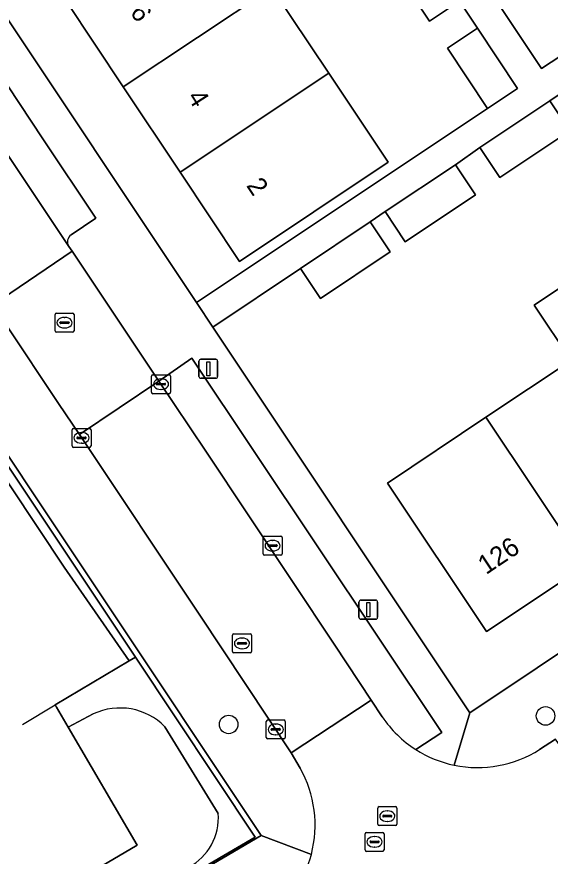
# Model space of a CAD drawing. Extents: x 158352 to 159489, y 383828 to 384603.
# Drawn here: x 158728.21 to 158756.34, y 384163.88 to 384208.09 of the extents above; entities that cross this region are included whole.
import ezdxf

# ---------------------------------------------------------------- set-up
doc = ezdxf.new("R2010")
doc.units = 0
for name, color, linetype in [('IMGEO_Boom', 7, 'Continuous'), ('IMGEO_Erf', 7, 'Continuous'), ('IMGEO_Groenvoorziening', 7, 'Continuous'), ('IMGEO_Hek', 7, 'Continuous'), ('IMGEO_Kolk', 7, 'Continuous'), ('IMGEO_Lichtmast', 7, 'Continuous'), ('IMGEO_Pand', 7, 'Continuous'), ('IMGEO_Pand_nummerreeks', 7, 'Continuous'), ('IMGEO_Parkeervlak_open', 7, 'Continuous'), ('IMGEO_Rijbaan_lokaal_open', 7, 'Continuous'), ('IMGEO_Rioolput', 7, 'Continuous'), ('IMGEO_Voetpad_open', 7, 'Continuous')]:
    doc.layers.add(name, color=color, linetype=linetype)

msp = doc.modelspace()

# ---------------------------------------------------------------- linework, layer by layer
at = {"layer": 'IMGEO_Boom'}
for centre in [(158756.089, 384171.265), (158739.383, 384170.816)]:
    msp.add_circle(centre, 0.489, dxfattribs=at)
at = {"layer": 'IMGEO_Erf'}
for points in [[(158661.89, 384306.702), (158737.694, 384193.032), (158753.032, 384203.26), (158750.922, 384206.438), (158752.505, 384207.489), (158751.552, 384208.904), (158749.972, 384207.85), (158747.497, 384211.561)], [(158766.842, 384208.399), (158763.158, 384205.927), (158762.099, 384207.505), (158761.301, 384206.989), (158762.358, 384205.41), (158758.66, 384202.935), (158757.603, 384204.514), (158756.312, 384203.657), (158757.363, 384202.077), (158753.675, 384199.623), (158752.622, 384201.206), (158751.342, 384200.289), (158752.394, 384198.707), (158748.69, 384196.244), (158747.638, 384197.826), (158746.844, 384197.289), (158747.9, 384195.71), (158744.228, 384193.253), (158743.172, 384194.832), (158738.549, 384191.749), (158752.1, 384171.43), (158802.113, 384204.829), (158788.594, 384225.155)], [(158732.078, 384163.004), (158734.56, 384164.453), (158730.926, 384170.674), (158730.313, 384171.723), (158730.24, 384171.849), (158734.136, 384174.169), (158730.72, 384179.098), (158723.614, 384189.764), (158724.023, 384190.002), (158700.665, 384224.966)], [(158741.664, 384209.617), (158744.664, 384205.122), (158747.791, 384200.432), (158739.959, 384195.193), (158736.823, 384199.899), (158733.825, 384204.395), (158730.828, 384208.891)]]:
    msp.add_lwpolyline(points, dxfattribs=at)
msp.add_lwpolyline([(158762.429, 384193.318), (158767.425, 384196.648), (158771.909, 384199.638), (158776.904, 384202.967), (158781.884, 384206.291), (158786.38, 384209.294), (158792.699, 384213.514), (158795.295, 384209.606), (158794.187, 384208.841), (158796.785, 384204.942), (158791.593, 384201.478), (158787.135, 384198.42), (158782.117, 384195.154), (158777.123, 384191.822), (158772.673, 384188.781), (158767.646, 384185.498), (158762.68, 384182.121), (158758.17, 384179.174), (158752.974, 384175.706), (158747.751, 384183.533), (158752.949, 384186.999), (158757.435, 384189.983), (158755.483, 384192.906), (158760.477, 384196.241)], close=True, dxfattribs=at)
at = {"layer": 'IMGEO_Groenvoorziening'}
for points in [[(158734.468, 384174.367), (158740.785, 384164.877), (158709.334, 384146.504), (158709.408, 384146.369), (158741.091, 384164.958), (158724.283, 384190.153), (158724.023, 384190.002)], [(158724.023, 384190.002), (158723.614, 384189.764), (158730.72, 384179.098), (158734.136, 384174.169), (158734.468, 384174.367)]]:
    msp.add_lwpolyline(points, close=True, dxfattribs=at)
for points in [[(158737.445, 384190.113), (158735.708, 384188.905), (158738.187, 384185.214), (158744.988, 384174.983), (158746.896, 384172.098), (158747.48, 384171.214)], [(158749.247, 384169.495), (158750.617, 384170.393), (158737.445, 384190.113)], [(158740.785, 384164.877), (158734.468, 384174.367), (158734.136, 384174.169), (158730.24, 384171.849), (158730.313, 384171.723), (158730.926, 384170.674), (158732.248, 384171.369)], [(158732.248, 384171.369), (158730.926, 384170.674)], [(158730.926, 384170.674), (158734.56, 384164.453), (158732.078, 384163.004)], [(158736.023, 384170.696), (158738.832, 384166.131)], [(158738.832, 384166.131), (158736.023, 384170.696)], [(158737.281, 384163.293), (158733.448, 384161.127), (158731.081, 384159.768), (158721.07, 384154.017), (158720.134, 384154.397), (158718.086, 384153.373), (158717.208, 384152.173), (158716.184, 384151.5), (158715.101, 384151.178), (158714.37, 384151.178), (158710.698, 384149.022), (158711.217, 384148.102), (158709.118, 384146.897), (158709.334, 384146.504), (158740.785, 384164.877)]]:
    msp.add_lwpolyline(points, dxfattribs=at)
for centre, radius, start, end in [((158733.658, 384168.357), 3.326, 44.6918, 115.0914), ((158733.658, 384168.357), 3.326, 44.6918, 115.0914), ((158752.54, 384174.647), 6.115, 214.1597, 237.418), ((158735.866, 384165.909), 2.974, 298.4051, 4.2806), ((158735.866, 384165.909), 2.974, 298.4051, 4.2806)]:
    msp.add_arc(centre, radius, start, end, dxfattribs=at)
at = {"layer": 'IMGEO_Hek'}
for points in [[(158734.468, 384174.367), (158724.023, 384190.002)], [(158730.24, 384171.849), (158734.136, 384174.169), (158734.468, 384174.367)], [(158740.785, 384164.877), (158734.468, 384174.367)], [(158728.508, 384170.817), (158730.24, 384171.849)], [(158709.334, 384146.504), (158740.785, 384164.877)]]:
    msp.add_lwpolyline(points, dxfattribs=at)
at = {"layer": 'IMGEO_Kolk'}
for p, q in [((158735.318, 384188.312), (158735.318, 384189.164)), ((158735.393, 384189.238), (158736.245, 384189.238)), ((158735.806, 384189.018), (158735.831, 384189.018)), ((158736.319, 384189.164), (158736.319, 384188.312)), ((158735.577, 384188.732), (158735.577, 384188.744)), ((158736.015, 384188.695), (158735.617, 384188.695)), ((158735.62, 384188.781), (158736.018, 384188.781)), ((158735.829, 384188.458), (158735.804, 384188.458)), ((158736.061, 384188.744), (158736.061, 384188.732)), ((158736.245, 384188.238), (158735.393, 384188.238)), ((158731.127, 384185.484), (158731.127, 384186.336)), ((158731.202, 384186.41), (158732.054, 384186.41)), ((158732.128, 384186.336), (158732.128, 384185.484)), ((158731.386, 384185.904), (158731.386, 384185.916)), ((158731.824, 384185.867), (158731.426, 384185.867)), ((158731.429, 384185.953), (158731.827, 384185.953)), ((158731.615, 384186.19), (158731.64, 384186.19)), ((158731.87, 384185.916), (158731.87, 384185.904)), ((158732.054, 384185.41), (158731.202, 384185.41)), ((158731.638, 384185.63), (158731.613, 384185.63)), ((158741.2, 384179.806), (158741.2, 384180.658)), ((158741.275, 384180.732), (158742.127, 384180.732)), ((158741.688, 384180.512), (158741.713, 384180.512)), ((158742.201, 384180.658), (158742.201, 384179.806)), ((158741.459, 384180.226), (158741.459, 384180.238)), ((158741.897, 384180.189), (158741.499, 384180.189)), ((158741.502, 384180.275), (158741.9, 384180.275)), ((158741.943, 384180.238), (158741.943, 384180.226)), ((158742.127, 384179.732), (158741.275, 384179.732)), ((158741.711, 384179.952), (158741.686, 384179.952)), ((158741.365, 384170.127), (158741.365, 384170.979)), ((158741.44, 384171.053), (158742.292, 384171.053)), ((158741.853, 384170.833), (158741.878, 384170.833)), ((158742.366, 384170.979), (158742.366, 384170.127)), ((158741.624, 384170.547), (158741.624, 384170.559)), ((158742.062, 384170.51), (158741.664, 384170.51)), ((158741.667, 384170.596), (158742.065, 384170.596)), ((158742.108, 384170.559), (158742.108, 384170.547)), ((158742.292, 384170.053), (158741.44, 384170.053)), ((158741.876, 384170.273), (158741.851, 384170.273))]:
    msp.add_line(p, q, dxfattribs=at)
for points in [[(158735.318, 384188.312), (158735.318, 384189.164)], [(158735.393, 384189.238), (158736.245, 384189.238)], [(158736.319, 384189.164), (158736.319, 384188.312)], [(158736.245, 384188.238), (158735.393, 384188.238)], [(158731.127, 384185.484), (158731.127, 384186.336)], [(158731.202, 384186.41), (158732.054, 384186.41)], [(158732.128, 384186.336), (158732.128, 384185.484)], [(158732.054, 384185.41), (158731.202, 384185.41)], [(158741.2, 384179.806), (158741.2, 384180.658)], [(158741.275, 384180.732), (158742.127, 384180.732)], [(158742.201, 384180.658), (158742.201, 384179.806)], [(158742.127, 384179.732), (158741.275, 384179.732)], [(158741.365, 384170.127), (158741.365, 384170.979)], [(158741.44, 384171.053), (158742.292, 384171.053)], [(158742.366, 384170.979), (158742.366, 384170.127)], [(158742.292, 384170.053), (158741.44, 384170.053)]]:
    msp.add_lwpolyline(points, dxfattribs=at)
for centre, radius, start, end in [((158735.395, 384189.162), 0.0765, 91.552, 178.448), ((158735.395, 384189.162), 0.0765, 91.552, 178.448), ((158736.243, 384189.162), 0.0765, 1.552, 88.448), ((158736.243, 384189.162), 0.0765, 1.552, 88.448), ((158735.617, 384188.741), 0.0403, 85.8775, 175.7526), ((158735.614, 384188.731), 0.0366, 178.938, 274.7102), ((158736.018, 384188.738), 0.043, 264.8664, 352.4533), ((158736.022, 384188.743), 0.0386, 1.7309, 96.639), ((158735.395, 384188.314), 0.0765, 181.552, 268.448), ((158735.395, 384188.314), 0.0765, 181.552, 268.448), ((158736.243, 384188.314), 0.0765, 271.552, 358.448), ((158736.243, 384188.314), 0.0765, 271.552, 358.448), ((158731.204, 384186.334), 0.0765, 91.552, 178.448), ((158731.204, 384186.334), 0.0765, 91.552, 178.448), ((158732.052, 384186.334), 0.0765, 1.552, 88.448), ((158732.052, 384186.334), 0.0765, 1.552, 88.448), ((158731.426, 384185.913), 0.0403, 85.8775, 175.7526), ((158731.423, 384185.903), 0.0366, 178.938, 274.7102), ((158731.827, 384185.91), 0.043, 264.8664, 352.4533), ((158731.831, 384185.915), 0.0386, 1.7309, 96.639), ((158731.204, 384185.486), 0.0765, 181.552, 268.448), ((158731.204, 384185.486), 0.0765, 181.552, 268.448), ((158732.052, 384185.486), 0.0765, 271.552, 358.448), ((158732.052, 384185.486), 0.0765, 271.552, 358.448), ((158741.277, 384180.656), 0.0765, 91.552, 178.448), ((158741.277, 384180.656), 0.0765, 91.552, 178.448), ((158742.125, 384180.656), 0.0765, 1.552, 88.448), ((158742.125, 384180.656), 0.0765, 1.552, 88.448), ((158741.499, 384180.235), 0.0403, 85.8775, 175.7526), ((158741.496, 384180.225), 0.0366, 178.938, 274.7102), ((158741.9, 384180.232), 0.043, 264.8664, 352.4533), ((158741.904, 384180.237), 0.0386, 1.7309, 96.639), ((158741.277, 384179.808), 0.0765, 181.552, 268.448), ((158741.277, 384179.808), 0.0765, 181.552, 268.448), ((158742.125, 384179.808), 0.0765, 271.552, 358.448), ((158742.125, 384179.808), 0.0765, 271.552, 358.448), ((158741.442, 384170.977), 0.0765, 91.552, 178.448), ((158741.442, 384170.977), 0.0765, 91.552, 178.448), ((158742.29, 384170.977), 0.0765, 1.552, 88.448), ((158742.29, 384170.977), 0.0765, 1.552, 88.448), ((158741.664, 384170.556), 0.0403, 85.8775, 175.7526), ((158741.661, 384170.546), 0.0366, 178.938, 274.7102), ((158742.065, 384170.553), 0.043, 264.8664, 352.4533), ((158742.069, 384170.558), 0.0386, 1.7309, 96.639), ((158741.442, 384170.129), 0.0765, 181.552, 268.448), ((158741.442, 384170.129), 0.0765, 181.552, 268.448), ((158742.29, 384170.129), 0.0765, 271.552, 358.448), ((158742.29, 384170.129), 0.0765, 271.552, 358.448)]:
    msp.add_arc(centre, radius, start, end, dxfattribs=at)
for centre, major_axis, ratio, start_param, end_param in [((158735.805, 384188.738), (-0.387, 0.002), 0.722429, 4.712389, 7.853982), ((158735.83, 384188.738), (-0.39, 0.002), 0.717154, 1.570796, 4.712389), ((158731.614, 384185.91), (-0.387, 0.002), 0.722429, 4.712389, 7.853982), ((158731.639, 384185.91), (-0.39, 0.002), 0.717154, 1.570796, 4.712389), ((158741.687, 384180.232), (-0.387, 0.002), 0.722429, 4.712389, 7.853982), ((158741.712, 384180.232), (-0.39, 0.002), 0.717154, 1.570796, 4.712389), ((158741.852, 384170.553), (-0.387, 0.002), 0.722429, 4.712389, 7.853982), ((158741.877, 384170.553), (-0.39, 0.002), 0.717154, 1.570796, 4.712389)]:
    msp.add_ellipse(centre, major_axis=major_axis, ratio=ratio, start_param=start_param, end_param=end_param, dxfattribs=at)
at = {"layer": 'IMGEO_Lichtmast'}
for p, q in [((158737.813, 384189.147), (158737.813, 384189.947)), ((158737.813, 384189.947), (158737.813, 384189.147)), ((158737.913, 384190.047), (158738.703, 384190.047)), ((158738.703, 384190.047), (158737.913, 384190.047)), ((158738.803, 384189.947), (158738.803, 384189.147)), ((158738.803, 384189.147), (158738.803, 384189.947)), ((158738.703, 384189.047), (158737.913, 384189.047)), ((158737.913, 384189.047), (158738.703, 384189.047)), ((158746.248, 384176.461), (158746.248, 384177.261)), ((158746.248, 384177.261), (158746.248, 384176.461)), ((158746.348, 384177.361), (158747.138, 384177.361)), ((158747.138, 384177.361), (158746.348, 384177.361)), ((158747.238, 384177.261), (158747.238, 384176.461)), ((158747.238, 384176.461), (158747.238, 384177.261)), ((158747.138, 384176.361), (158746.348, 384176.361)), ((158746.348, 384176.361), (158747.138, 384176.361))]:
    msp.add_line(p, q, dxfattribs=at)
for points in [[(158738.233, 384189.922), (158738.383, 384189.922), (158738.383, 384189.172), (158738.233, 384189.172), (158738.233, 384189.922)], [(158746.668, 384177.236), (158746.818, 384177.236), (158746.818, 384176.486), (158746.668, 384176.486), (158746.668, 384177.236)]]:
    msp.add_lwpolyline(points, dxfattribs=at)
for centre, start, end in [((158737.913, 384189.947), 90, 180), ((158737.913, 384189.947), 90, 180), ((158738.703, 384189.947), 0, 90), ((158738.703, 384189.947), 360, 90), ((158737.913, 384189.147), 180, 270), ((158737.913, 384189.147), 180, 270), ((158738.703, 384189.147), 270, 0), ((158738.703, 384189.147), 270, 0), ((158746.348, 384177.261), 90, 180), ((158746.348, 384177.261), 90, 180), ((158747.138, 384177.261), 0, 90), ((158747.138, 384177.261), 360, 90), ((158746.348, 384176.461), 180, 270), ((158746.348, 384176.461), 180, 270), ((158747.138, 384176.461), 270, 0), ((158747.138, 384176.461), 270, 0)]:
    msp.add_arc(centre, 0.1, start, end, dxfattribs=at)
at = {"layer": 'IMGEO_Pand'}
for points in [[(158741.664, 384209.617), (158741.545, 384209.795), (158743.534, 384211.122), (158740.737, 384215.314), (158738.748, 384213.988), (158738.665, 384214.113), (158730.828, 384208.891), (158733.825, 384204.395)], [(158749.972, 384207.85), (158751.552, 384208.904), (158749.077, 384212.615), (158747.497, 384211.561)], [(158733.825, 384204.395), (158736.823, 384199.899), (158744.664, 384205.122), (158741.664, 384209.617)], [(158753.032, 384203.26), (158754.615, 384204.311), (158752.505, 384207.489), (158750.922, 384206.438)], [(158744.664, 384205.122), (158736.823, 384199.899), (158739.959, 384195.193), (158747.791, 384200.432)], [(158753.675, 384199.623), (158757.363, 384202.077), (158756.312, 384203.657), (158752.622, 384201.206)], [(158748.69, 384196.244), (158752.394, 384198.707), (158751.342, 384200.289), (158747.638, 384197.826)], [(158744.228, 384193.253), (158747.9, 384195.71), (158746.844, 384197.289), (158743.172, 384194.832)], [(158762.429, 384193.318), (158760.477, 384196.241), (158755.483, 384192.906), (158757.435, 384189.983), (158762.68, 384182.121), (158767.646, 384185.498)], [(158762.68, 384182.121), (158757.435, 384189.983), (158752.949, 384186.999), (158758.17, 384179.174)], [(158752.949, 384186.999), (158747.751, 384183.533), (158752.974, 384175.706), (158758.17, 384179.174)]]:
    msp.add_lwpolyline(points, close=True, dxfattribs=at)
at = {"layer": 'IMGEO_Parkeervlak_open'}
for points in [[(158731.078, 384196.607), (158732.384, 384197.474), (158729.586, 384201.665), (158723.424, 384210.977), (158701.545, 384243.711)], [(158699.65, 384242.943), (158727.586, 384201.054), (158730.963, 384195.982)], [(158745.185, 384229.466), (158741.472, 384226.964), (158755.874, 384205.363), (158760.063, 384208.099), (158745.402, 384230.033)]]:
    msp.add_lwpolyline(points, dxfattribs=at)
msp.add_arc((158731.352, 384196.233), 0.463, 126.2731, 212.8753, dxfattribs=at)
at = {"layer": 'IMGEO_Rijbaan_lokaal_open'}
for points in [[(158699.65, 384242.943), (158697.726, 384245.831), (158693.511, 384243.056), (158726.672, 384193.344), (158726.698, 384193.304), (158726.954, 384192.921), (158731.127, 384195.741), (158730.963, 384195.982), (158727.586, 384201.054)], [(158731.127, 384195.741), (158726.954, 384192.921), (158727.659, 384191.863), (158730.422, 384187.719), (158731.514, 384186.085), (158735.708, 384188.905)], [(158738.187, 384185.214), (158735.708, 384188.905), (158731.514, 384186.085), (158737.872, 384176.577), (158742.673, 384169.326), (158746.896, 384172.098), (158744.988, 384174.983)]]:
    msp.add_lwpolyline(points, close=True, dxfattribs=at)
for points in [[(158747.48, 384171.214), (158746.896, 384172.098), (158742.673, 384169.326), (158743.162, 384168.514)], [(158753.215, 384162.703), (158754.1, 384161.357), (158756.455, 384162.969), (158759.872, 384165.217), (158759.023, 384166.554), (158757.561, 384168.674), (158756.613, 384170.048), (158755.775, 384169.498)]]:
    msp.add_lwpolyline(points, dxfattribs=at)
for centre, radius, start, end in [((158752.54, 384174.647), 6.115, 214.1597, 237.418), ((158752.514, 384174.628), 6.085, 237.5202, 258.2851), ((158752.508, 384174.62), 6.075, 258.3337, 302.5361), ((158737.767, 384165.514), 6.173, 345.5251, 29.0756), ((158737.7, 384165.596), 6.258, 301.9381, 344.9514)]:
    msp.add_arc(centre, radius, start, end, dxfattribs=at)
at = {"layer": 'IMGEO_Rioolput'}
for p, q in [((158730.308, 384192.477), (158731.16, 384192.477)), ((158730.233, 384191.551), (158730.233, 384192.403)), ((158730.492, 384191.971), (158730.492, 384191.983)), ((158730.535, 384192.02), (158730.933, 384192.02)), ((158730.721, 384192.257), (158730.746, 384192.257)), ((158730.976, 384191.983), (158730.976, 384191.971)), ((158731.234, 384192.403), (158731.234, 384191.551)), ((158730.93, 384191.934), (158730.532, 384191.934)), ((158730.744, 384191.697), (158730.719, 384191.697)), ((158731.16, 384191.477), (158730.308, 384191.477)), ((158739.585, 384174.659), (158739.585, 384175.511)), ((158739.66, 384175.585), (158740.512, 384175.585)), ((158740.073, 384175.365), (158740.098, 384175.365)), ((158740.586, 384175.511), (158740.586, 384174.659)), ((158739.844, 384175.079), (158739.844, 384175.091)), ((158740.282, 384175.042), (158739.884, 384175.042)), ((158739.887, 384175.128), (158740.285, 384175.128)), ((158740.096, 384174.805), (158740.071, 384174.805)), ((158740.328, 384175.091), (158740.328, 384175.079)), ((158740.512, 384174.585), (158739.66, 384174.585)), ((158747.246, 384165.56), (158747.246, 384166.412)), ((158747.321, 384166.486), (158748.173, 384166.486)), ((158748.247, 384166.412), (158748.247, 384165.56)), ((158747.505, 384165.98), (158747.505, 384165.992)), ((158747.943, 384165.943), (158747.545, 384165.943)), ((158747.548, 384166.029), (158747.946, 384166.029)), ((158747.734, 384166.266), (158747.759, 384166.266)), ((158747.989, 384165.992), (158747.989, 384165.98)), ((158748.173, 384165.486), (158747.321, 384165.486)), ((158747.757, 384165.706), (158747.732, 384165.706)), ((158746.576, 384164.206), (158746.576, 384165.058)), ((158746.651, 384165.132), (158747.503, 384165.132)), ((158747.577, 384165.058), (158747.577, 384164.206)), ((158746.835, 384164.626), (158746.835, 384164.638)), ((158747.273, 384164.589), (158746.875, 384164.589)), ((158746.878, 384164.675), (158747.276, 384164.675)), ((158747.064, 384164.912), (158747.089, 384164.912)), ((158747.319, 384164.638), (158747.319, 384164.626)), ((158747.503, 384164.132), (158746.651, 384164.132)), ((158747.087, 384164.352), (158747.062, 384164.352))]:
    msp.add_line(p, q, dxfattribs=at)
for points in [[(158730.308, 384192.477), (158731.16, 384192.477)], [(158730.233, 384191.551), (158730.233, 384192.403)], [(158731.234, 384192.403), (158731.234, 384191.551)], [(158731.16, 384191.477), (158730.308, 384191.477)], [(158739.585, 384174.659), (158739.585, 384175.511)], [(158739.66, 384175.585), (158740.512, 384175.585)], [(158740.586, 384175.511), (158740.586, 384174.659)], [(158740.512, 384174.585), (158739.66, 384174.585)], [(158747.246, 384165.56), (158747.246, 384166.412)], [(158747.321, 384166.486), (158748.173, 384166.486)], [(158748.247, 384166.412), (158748.247, 384165.56)], [(158748.173, 384165.486), (158747.321, 384165.486)], [(158746.576, 384164.206), (158746.576, 384165.058)], [(158746.651, 384165.132), (158747.503, 384165.132)], [(158747.577, 384165.058), (158747.577, 384164.206)], [(158747.503, 384164.132), (158746.651, 384164.132)]]:
    msp.add_lwpolyline(points, dxfattribs=at)
for centre, radius, start, end in [((158730.31, 384192.401), 0.0765, 91.552, 178.448), ((158730.31, 384192.401), 0.0765, 91.552, 178.448), ((158731.158, 384192.401), 0.0765, 1.552, 88.448), ((158731.158, 384192.401), 0.0765, 1.552, 88.448), ((158730.532, 384191.98), 0.0403, 85.8775, 175.7526), ((158730.937, 384191.982), 0.0386, 1.7309, 96.639), ((158730.31, 384191.553), 0.0765, 181.552, 268.448), ((158730.31, 384191.553), 0.0765, 181.552, 268.448), ((158730.529, 384191.97), 0.0366, 178.938, 274.7102), ((158730.933, 384191.977), 0.043, 264.8664, 352.4533), ((158731.158, 384191.553), 0.0765, 271.552, 358.448), ((158731.158, 384191.553), 0.0765, 271.552, 358.448), ((158739.662, 384175.509), 0.0765, 91.552, 178.448), ((158739.662, 384175.509), 0.0765, 91.552, 178.448), ((158740.51, 384175.509), 0.0765, 1.552, 88.448), ((158740.51, 384175.509), 0.0765, 1.552, 88.448), ((158739.884, 384175.088), 0.0403, 85.8775, 175.7526), ((158739.881, 384175.078), 0.0366, 178.938, 274.7102), ((158740.285, 384175.085), 0.043, 264.8664, 352.4533), ((158740.289, 384175.09), 0.0386, 1.7309, 96.639), ((158739.662, 384174.661), 0.0765, 181.552, 268.448), ((158739.662, 384174.661), 0.0765, 181.552, 268.448), ((158740.51, 384174.661), 0.0765, 271.552, 358.448), ((158740.51, 384174.661), 0.0765, 271.552, 358.448), ((158747.323, 384166.41), 0.0765, 91.552, 178.448), ((158747.323, 384166.41), 0.0765, 91.552, 178.448), ((158748.171, 384166.41), 0.0765, 1.552, 88.448), ((158748.171, 384166.41), 0.0765, 1.552, 88.448), ((158747.545, 384165.989), 0.0403, 85.8775, 175.7526), ((158747.542, 384165.979), 0.0366, 178.938, 274.7102), ((158747.946, 384165.986), 0.043, 264.8664, 352.4533), ((158747.95, 384165.991), 0.0386, 1.7309, 96.639), ((158747.323, 384165.562), 0.0765, 181.552, 268.448), ((158747.323, 384165.562), 0.0765, 181.552, 268.448), ((158748.171, 384165.562), 0.0765, 271.552, 358.448), ((158748.171, 384165.562), 0.0765, 271.552, 358.448), ((158746.653, 384165.056), 0.0765, 91.552, 178.448), ((158746.653, 384165.056), 0.0765, 91.552, 178.448), ((158747.501, 384165.056), 0.0765, 1.552, 88.448), ((158747.501, 384165.056), 0.0765, 1.552, 88.448), ((158746.875, 384164.635), 0.0403, 85.8775, 175.7526), ((158746.872, 384164.625), 0.0366, 178.938, 274.7102), ((158747.276, 384164.632), 0.043, 264.8664, 352.4533), ((158747.28, 384164.637), 0.0386, 1.7309, 96.639), ((158746.653, 384164.208), 0.0765, 181.552, 268.448), ((158746.653, 384164.208), 0.0765, 181.552, 268.448), ((158747.501, 384164.208), 0.0765, 271.552, 358.448), ((158747.501, 384164.208), 0.0765, 271.552, 358.448)]:
    msp.add_arc(centre, radius, start, end, dxfattribs=at)
for centre, major_axis, ratio, start_param, end_param in [((158730.72, 384191.977), (-0.387, 0.002), 0.722429, 4.712389, 7.853982), ((158730.745, 384191.977), (-0.39, 0.002), 0.717154, 1.570796, 4.712389), ((158740.072, 384175.085), (-0.387, 0.002), 0.722429, 4.712389, 7.853982), ((158740.097, 384175.085), (-0.39, 0.002), 0.717154, 1.570796, 4.712389), ((158747.733, 384165.986), (-0.387, 0.002), 0.722429, 4.712389, 7.853982), ((158747.758, 384165.986), (-0.39, 0.002), 0.717154, 1.570796, 4.712389), ((158747.063, 384164.632), (-0.387, 0.002), 0.722429, 4.712389, 7.853982), ((158747.088, 384164.632), (-0.39, 0.002), 0.717154, 1.570796, 4.712389)]:
    msp.add_ellipse(centre, major_axis=major_axis, ratio=ratio, start_param=start_param, end_param=end_param, dxfattribs=at)
at = {"layer": 'IMGEO_Voetpad_open'}
for points in [[(158751.279, 384168.67), (158752.1, 384171.43), (158738.549, 384191.749), (158737.694, 384193.032), (158661.89, 384306.702)], [(158700.214, 384242.829), (158701.545, 384243.711), (158723.424, 384210.977), (158729.586, 384201.665), (158732.384, 384197.474), (158731.078, 384196.607)], [(158747.348, 384238.972), (158751.24, 384241.602), (158769.384, 384214.37), (158765.045, 384211.446), (158760.063, 384208.099), (158755.874, 384205.363), (158741.472, 384226.964), (158745.185, 384229.466)], [(158690.826, 384240.042), (158724.283, 384190.153), (158741.091, 384164.958), (158743.744, 384163.971)], [(158731.514, 384186.085), (158730.422, 384187.719), (158727.659, 384191.863), (158726.954, 384192.921), (158726.698, 384193.304), (158726.672, 384193.344), (158724.158, 384191.674), (158723.203, 384193.119), (158723.935, 384193.618), (158717.101, 384203.875), (158716.422, 384203.452), (158715.231, 384205.228), (158715.978, 384205.729), (158702.247, 384226.201)], [(158751.552, 384208.904), (158752.505, 384207.489), (158754.615, 384204.311), (158753.032, 384203.26), (158737.694, 384193.032), (158738.549, 384191.749), (158743.172, 384194.832), (158746.844, 384197.289), (158747.638, 384197.826), (158751.342, 384200.289), (158752.622, 384201.206), (158756.312, 384203.657), (158757.603, 384204.514), (158761.301, 384206.989), (158762.099, 384207.505), (158765.784, 384209.977)], [(158803.252, 384209.588), (158801.917, 384208.691), (158802.113, 384204.829), (158752.1, 384171.43), (158751.279, 384168.67)], [(158730.963, 384195.982), (158731.127, 384195.741), (158735.708, 384188.905), (158737.445, 384190.113), (158750.617, 384170.393), (158749.247, 384169.495)], [(158743.162, 384168.514), (158742.673, 384169.326), (158737.872, 384176.577), (158731.514, 384186.085)], [(158755.775, 384169.498), (158756.613, 384170.048)], [(158743.744, 384163.971), (158741.091, 384164.958), (158709.408, 384146.369), (158706.962, 384144.94), (158705.582, 384144.133), (158687.07, 384133.326), (158684.077, 384131.578), (158669.108, 384122.84), (158667.746, 384122.045), (158663.493, 384119.562), (158658.71, 384116.77), (158649.271, 384111.259), (158644.581, 384108.521), (158640.005, 384105.85), (158634.558, 384102.668), (158635.177, 384101.653), (158631.769, 384099.592), (158631.113, 384100.657), (158615.79, 384091.707)]]:
    msp.add_lwpolyline(points, dxfattribs=at)
for centre, radius, start, end in [((158731.352, 384196.233), 0.463, 126.2731, 212.8753), ((158752.514, 384174.628), 6.085, 237.5202, 258.2851), ((158752.508, 384174.62), 6.075, 258.3337, 302.5361), ((158737.767, 384165.514), 6.173, 345.5251, 29.0756), ((158737.7, 384165.596), 6.258, 301.9381, 344.9514)]:
    msp.add_arc(centre, radius, start, end, dxfattribs=at)

# ---------------------------------------------------------------- texts
at = {"layer": 'IMGEO_Pand_nummerreeks'}
for s, rotation, p in [('6', 304.022, (158734.154, 384208.336)), ('4', 302.6322, (158737.174, 384203.855)), ('2', 303.3613, (158740.29, 384199.201)), ('126', 33.8305, (158752.955, 384178.681))]:
    msp.add_text(s, height=1, rotation=rotation, dxfattribs=at).set_placement(p)

doc.saveas('drawing.dxf')
